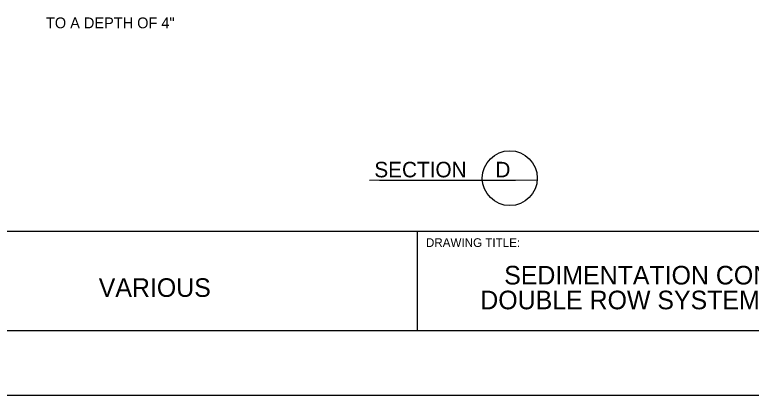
# Model space of a CAD drawing. Extents: x 0 to 2.83, y -0.06 to 1.83.
# Drawn here: x 1.786 to 2.379, y 0 to 0.307 of the extents above; entities that cross this region are included whole.
import ezdxf

# ---------------------------------------------------------------- set-up
doc = ezdxf.new("R2010")
doc.units = 0
for name, color, linetype in [('BDR_Inner_Perimeter', 7, 'Continuous'), ('BDR_Scale_As_Noted', 7, 'Continuous'), ('BDR_Title_Block', 7, 'Continuous'), ('CT_Text', 7, 'Continuous'), ('Edge_of_Truck_Apron', 7, 'Continuous'), ('Existing Soil', 7, 'Continuous'), ('Longitudinal Joint', 7, 'Continuous')]:
    doc.layers.add(name, color=color, linetype=linetype)

msp = doc.modelspace()

# ---------------------------------------------------------------- linework, layer by layer
at = {"layer": 'BDR_Inner_Perimeter'}
msp.add_lwpolyline([(0.13539, 1.78125), (2.78123, 1.78125), (2.78123, 0.05208), (0.13539, 0.05208)], close=True, dxfattribs=at)
at = {"layer": 'BDR_Scale_As_Noted'}
msp.add_lwpolyline([(0, 0), (2.83333, 0), (2.83333, 1.83333), (0, 1.83333)], close=True, dxfattribs=at)
msp.add_lwpolyline([(0, 0), (2.83333, 0), (2.83333, 1.83333), (0, 1.83333)], close=True, dxfattribs=at)
at = {"layer": 'BDR_Title_Block'}
for p, q in [((2.78123, 0.13208), (0.13539, 0.13208)), ((2.10977, 0.13208), (2.10977, 0.05208))]:
    msp.add_line(p, q, dxfattribs=at)
at = {"layer": 'CT_Text'}
msp.add_circle((2.18434, 0.17504), 0.02214, dxfattribs=at)
at = {"layer": 'Edge_of_Truck_Apron'}
for p in [(2.07936, 0.17346), (2.08162, 0.17346)]:
    msp.add_line(p, (2.18576, 0.17355), dxfattribs=at)
at = {"layer": 'Existing Soil'}
msp.add_line((2.07133, 0.17345), (2.20621, 0.17356), dxfattribs=at)
at = {"layer": 'Longitudinal Joint'}
msp.add_line((2.10036, 0.17348), (2.18904, 0.17355), dxfattribs=at)

# ---------------------------------------------------------------- texts
at = {"layer": 'BDR_Title_Block'}
for s, height, p in [('DRAWING TITLE:', 0.007, (2.11677, 0.11958)), ('SEDIMENTATION CONTROL ', 0.015, (2.17981, 0.08933)), ('VARIOUS', 0.015, (1.85319, 0.07933)), ('DOUBLE ROW SYSTEMS SHEET 2 ', 0.015, (2.16056, 0.06933))]:
    msp.add_text(s, height=height, dxfattribs=at).set_placement(p)
at = {"layer": 'Edge_of_Truck_Apron'}
msp.add_text('TO A DEPTH OF 4"', height=0.00875, dxfattribs=at).set_placement((1.81069, 0.29586))
at = {"layer": 'Longitudinal Joint'}
msp.add_text('SECTION     D', height=0.0125, rotation=360, dxfattribs=at).set_placement((2.07521, 0.17571))

doc.saveas('drawing.dxf')
